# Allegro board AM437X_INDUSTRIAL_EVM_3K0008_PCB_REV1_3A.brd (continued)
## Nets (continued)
DGND: C3.2 C4.2 C5.2 C6.2 C7.2 C8.2 C9.2 C10.2 C11.2 C12.2 C13.2 C14.2 C16.2 C17.2 C18.2 C19.2 C20.2 C21.2 C22.2 C23.2 C24.2 C25.2 C26.2 C27.2(NEG) C28.2 C29.2 C30.2 C31.2 C32.2 C33.2 C34.2 C37.2 C38.2 C39.2 C40.2 C41.2 C43.2 C44.2 C45.2 C46.2 C47.2 C48.2 C49.2 C50.2 C52.2 C53.2 C58.2 C59.2 C60.2 C61.2 C62.2 C63.2 C64.2 C65.2 C66.2 C68.2 C69.2 C70.2 C71.2 C72.2 C73.2 C74.2 C75.2 C76.2 C77.2 C78.2 C79.2 C80.2 C81.2 C82.2 C83.2 C84.2 C85.2 C86.2 C87.2 C89.2 C90.2 C91.2 C92.2 C93.2 C95.2 C96.2 C97.2 C98.2 C100.2 C101.2 C102.2 C103.2 C104.2 C105.2 C106.2 C107.2 C108.2 C109.2 C110.2 C111.2 C112.2 C113.2 C114.2 C115.2 C116.2 C117.2 C118.2 C119.2 C120.2 C121.1 C122.1 C123.2 C124.2 C125.2 C126.2 C127.2 C128.2 C129.1 C130.1 C131.2(NEG) C132.2 C133.2 C134.2 C136.2 C137.1 C138.2 C139.2 C140.2 C141.2 C142.2 C143.2 C144.2 C145.2 C146.2 C147.2 C148.2 C149.2 C150.2 C151.2 C152.2 C153.2 C154.2 C155.2 C156.2 C157.2 C158.2 C159.2 C160.2 C161.2 C162.2 C163.2 C164.2 C165.2 C166.2 C167.2 C168.2 C169.2 C170.2 C171.2 C172.2 C173.2 C174.2 C175.2 C176.2 C177.2 C178.2 C179.2 C180.2 C181.2 C182.2 C183.2 C184.2 C185.2 C186.2 C187.2 C188.1 C189.2 C190.2 C191.2 C192.2 C193.2 C194.2 C195.2 C196.2 C197.2 C198.2 C199.2 C200.2 C201.2 C202.2 C203.2 C204.2 C205.2 C206.2 C207.2 C208.2 C209.2 C210.2 C211.2 C212.2 C213.2 C214.2 C215.2 C216.2 C218.2 C219.2 C220.2 C221.2 C222.2 C223.2 C224.2 C225.2 C226.2 C227.2 C228.2 C229.2 C230.2 C231.2 C232.2 C233.2 C234.2 C235.2 C236.2 C237.2 C238.2 C239.2 C240.2 C241.2 C242.2 C244.2 C245.1 C246.1 C249.2 C250.1 C251.1 C252.2 C254.2 C255.2 C256.2 C257.2 C258.2 C259.2 C260.1 C261.2 C262.2 C263.2 C264.2 C265.2 C266.2 C267.2 C268.2 C269.2 C271.2(NEG) C272.2 C273.2 C274.1 C275.1 C276.2 C277.2 C278.2 C279.2 C280.2 C281.2 C282.2 C283.2 C284.2 C285.2 C286.2 C287.2 C288.2 C289.2 C290.2 C291.2 C292.2 C293.2 C294.2 C295.2 C296.2 C297.2 C299.2 C301.2 C302.2 C303.2 C304.2 C307.2 C309.2 C311.2 C312.2 C314.2 C315.2 C316.2 C318.2 C319.2 C320.2 C321.2 C322.2(NEG) C323.2 C324.2 C325.2 C326.2 C327.2 C328.2 C329.2 C330.2 C333.2 C334.2 C335.2 C336.2 C337.2 C338.2 C339.2 C340.2(NEG) C341.2 C342.2 C343.2 C344.2 C345.2 C346.2 C347.2 C348.2 C349.2 C350.2 C351.2 C352.2 D1.2(ANODE) D2.1(CATHODE) D11.2(ANODE) D13.2(ANODE) D14.2(ANODE) D15.1(CATHODE) D16.2(ANODE) D18.2(ANODE) D21.2(ANODE) D22.2(ANODE) FB12.2 J1.17 J1.29 J1.30 J3.10 J4.1 J4.12 J4.13 J5.5 J5.7 J6.8 J7.8(GND#8) J7.12(GND#12) J7.16(GND#16) J7.20(GND#20) J8.2 J9.8 J12.2 J12.3 J13.2 J15.6 J16.22 J16.39 J16.40 J16.59 J16.60 J18.5(GND) J19.6(VSS) J19.9(GND) J19.11(GND3) J19.12(GND4) J19.13(GND5) J19.14(GND6) J19.15(GND7) J19.16(GND8) Q1.S(SOURCE) Q2.S(SOURCE) Q3.S(SOURCE) Q4.S(SOURCE) Q5.S(SOURCE) Q6.S(SOURCE) Q7.S(SOURCE) Q8.S(SOURCE) R1.1(P1) R7.1(P1) R9.1(P1) R11.1(P1) R17.1(P1) R18.1(P1) R19.2 R32.2 R33.1(P1) R34.1(P1) R44.1(P1) R45.1(P1) R46.1(P1) R51.1(P1) R53.1(P1) R55.1(P1) R57.1(P1) R81.1(P1) R93.2 R94.1(P1) R108.1(P1) R112.1(P1) R122.1(P1) R127.1(P1) R130.1(P1) R156.1(P1) R160.1(P1) R162.1(P1) R166.1(P1) R169.1(P1) R172.1(P1) R175.1(P1) R176.1(P1) R181.1(P1) R182.1(P1) R185.1(P1) R191.1(P1) R192.1(P1) R197.2(P2) R198.1(P1) R202.1(P1) R212.1(P1) R213.1(P1) R274.1(P1) R276.1(P1) R278.1(P1) R301.1(P1) R304.1(P1) R314.1(P1) R315.1(P1) R316.1(P1) R317.1(P1) R318.1(P1) R319.1(P1) R320.1(P1) R321.1(P1) R322.1(P1) R328.1(P1) R329.1(P1) R330.1(P1) R331.1(P1) R332.1(P1) R333.1(P1) R334.1(P1) R335.1(P1) R340.1(P1) R341.1(P1) R342.1(P1) R362.1(P1) R366.1(P1) R369.1(P1) R372.1(P1) R394.1(P1) R397.1(P1) R398.1(P1) R429.1(P1) R433.1(P1) R444.1(P1) R452.1(P1) R460.2(P2) R464.1(P1) R474.2 R476.1(P1) R504.1(P1) R509.1(P1) R511.1(P1) R513.2(P2) R515.2(P2) R518.1(P1) R539.1(P1) R541.2(P2) R543.1(P1) R549.1(P1) R550.1(P1) R551.1(P1) R553.1(P1) R554.1(P1) R555.1(P1) R556.1(P1) R557.1(P1) R566.2(P2) SW1.3 SW1.4 SW2.1 SW2.2 TP1.1 TP9.1 TP11.1 TP16.1 U3.7(GND) U4.28(GND) U4.TH_PD(THRM) U5.7(A2) U5.8(G\) U5.9(A0) U5.10(A1) U5.16(GND) U6.2(DIR) U6.11(GND#11) U6.12(GND#12) U6.13(GND#13) U7.TPAD U8.3(GND) U9.10(GND) U10.7(GND) U11.A1(GND#A1) U11.A25(GND#A25) U11.AA23(TEST_EN) U11.AE1(GND#AE1) U11.AE25(GND#AE25) U11.H15(GND#H15) U11.H18(GND#H18) U11.J9(GND#J9) U11.J12(GND#J12) U11.J15(GND#J15) U11.J17(GND#J17) U11.K9(GND#K9) U11.K11(GND#K11) U11.K12(GND#K12) U11.K14(GND#K14) U11.K15(GND#K15) U11.L8(GND#L8) U11.L9(GND#L9) U11.L11(GND#L11) U11.L15(GND#L15) U11.L17(GND#L17) U11.L18(GND#L18) U11.M10(GND#M10) U11.M11(GND#M11) U11.M13(GND#M13) U11.M15(GND#M15) U11.M16(GND#M16) U11.N10(GND#N10) U11.N11(GND#N11) U11.N12(GND#N12) U11.N13(GND#N13) U11.N14(GND#N14) U11.N15(GND#N15) U11.P8(GND#P8) U11.P9(GND#P9) U11.P10(GND#P10) U11.P11(GND#P11) U11.P12(GND#P12) U11.P13(GND#P13) U11.P14(GND#P14) U11.P15(GND#P15) U11.R12(GND#R12) U11.R15(GND#R15) U11.R17(GND#R17) U11.R18(GND#R18) U11.T12(GND#T12) U11.T15(GND#T15) U11.T17(GND#T17) U11.U8(GND#U8) U11.U9(GND#U9) U11.U10(GND#U10) U11.U11(GND#U11) U11.U12(GND#U12) U11.U13(GND#U13) U11.U14(GND#U14) U11.U16(GND#U16) U11.U17(GND#U17) U11.U18(GND#U18) U11.U19(GND#U19) U11.V9(GND#V9) U11.V10(GND#V10) U11.V11(GND#V11) U11.V12(GND#V12) U11.V13(GND#V13) U11.V14(GND#V14) U11.V18(GND#V18) U11.W23(VSSA_USB) U12.TPAD U13.1(GND.1) U13.5(GND.2) U13.10(AGND) U13.11(GND.3) U13.13(TEST) U13.15(GND.4) U13.25(GND.5) U13.35(GND.6) U13.47(GND.7) U13.51(GND.8) U14.7(GND) U15.7(GND) U16.5(VSS) U16.7(NC1) U17.7(GND) U18.2(V-) U19.2(V-) U20.A9(VSS#A9) U20.B1(VSSQ#B1) U20.B3(VSS#B3) U20.B9(VSSQ#B9) U20.D1(VSSQ#D1) U20.D8(VSSQ#D8) U20.E1(VSS#E1) U20.E2(VSSQ#E2) U20.E8(VSSQ#E8) U20.F9(VSSQ#F9) U20.G1(VSSQ#G1) U20.G8(VSS#G8) U20.G9(VSSQ#G9) U20.J2(VSS#J2) U20.J8(VSS#J8) U20.M1(VSS#M1) U20.M9(VSS#M9) U20.P1(VSS#P1) U20.P9(VSS#P9) U20.T1(VSS#T1) U20.T9(VSS#T9) U21.A9(VSS#A9) U21.B1(VSSQ#B1) U21.B3(VSS#B3) U21.B9(VSSQ#B9) U21.D1(VSSQ#D1) U21.D8(VSSQ#D8) U21.E1(VSS#E1) U21.E2(VSSQ#E2) U21.E8(VSSQ#E8) U21.F9(VSSQ#F9) U21.G1(VSSQ#G1) U21.G8(VSS#G8) U21.G9(VSSQ#G9) U21.J2(VSS#J2) U21.J8(VSS#J8) U21.M1(VSS#M1) U21.M9(VSS#M9) U21.P1(VSS#P1) U21.P9(VSS#P9) U21.T1(VSS#T1) U21.T9(VSS#T9) U22.2(V-) U23.14(GND#14) U23.20(GND#20) U23.28(GND#28) U23.TPAD U24.2(V-) U25.4(PGND) U25.8(GND) U25.11(PWRPD) U26.6(SENSE4H) U26.12(GND) U26.TPAD U27.5(GND) U28.2(GND) U29.C1(GND) U30.2(GND) U31.2(GND) U32.1(A0) U32.2(A1) U32.3(A2) U32.4(VSS) U33.5(GND1) U33.10(GND2) U34.2(GND) U34.5(DIR) U35.A2(AGND) U35.C1(SENSEM) U35.C3(PGND#C3) U35.C4(PGND#C4) U35.D4(PGND#D4) U36.3(GND) U37.13(VSS_PS) U37.29(VSS) U37.49(P_GND) U38.3(2DIR) U38.8(GND#8) U38.9(GND#9) U38.14(2O\E\) U38.15(1O\E\) U39.10(GND) U40.C1(GND) U41.5(GND) U42.3(GND) U43.3(GND) U44.3(GND) U45.8(GND#8) U45.9(GND#9) U46.10(GND) U47.4(GND) U48.3(GND) U49.5(GND) U50.3(GND) U51.3(GND) U52.C1(GND) U53.C1(GND) U54.3(GND) U55.5(GND) U56.3(GND) U57.5(GND) U58.11(GND#11) U58.12(GND#12) U58.13(GND#13) U59.4(GND)
GND_ETH1: C121.2 C122.2 J4.SHLD1 J4.SHLD2
GND_OSC0: C35.2 C36.2 R566.1(P1) U11.B24(VSS_OSC)
GND_OSC1: C243.2 C248.2 U11.AD4(VSS_RTC)
GNDA_ADC: C54.2 C55.2 C56.2 C57.2 C217.2 J1.39 J1.40 J2.3 R58.1 R64.1 R68.1 R202.2(P2) R444.2(P2) U11.AC15(VSSA_ADC) U11.AD15(ADC1_VREFN) U11.AE14(ADC0_VREFN)
GNDUSBJ: FB12.1 J18.S1 J18.S2 J18.S3 J18.S4
V1_5D: C231.1 C233.1 C234.1 C236.1 C240.1 C241.1 C247.1 C276.1 C280.1 R313.2(P2) R470.1 R486.1(P1) R494.2(P2) U11.K7(VDD_DDR#K7) U11.K8(VDD_DDR#K8) U11.M7(VDD_DDR#M7) U11.M8(VDD_DDR#M8) U11.N7(VDD_DDR#N7) U11.N8(VDD_DDR#N8) U11.R6(VDD_DDR#R6) U11.R7(VDD_DDR#R7) U11.R8(VDD_DDR#R8) U11.T7(VDD_DDR#T7) U11.T8(VDD_DDR#T8) U11.V7(VDD_DDR#V7) U11.V8(VDD_DDR#V8)
V1_5DREG: C269.1 C273.1 L8.2 R480.2(P2) U52.A2(VIN#A2) U52.B2(VIN#B2)
V1_8D: C139.1 C168.1 FB1.2 Q1.G(GATE) R1.2(P2) R229.2(P2) R309.2(P2) R379.1(P1) R479.2(P2) U33.3(VDD)
V1_8D_AM437X: C31.1 C32.1 C158.1 C159.1 C160.1 C192.1 FB1.1 FB6.2 FB8.1 FB9.1 FB10.1 FB11.2 FB14.2 R142.2(P2) R149.2(P2) U11.C23(VDDS_OSC)
V1_8DADC: C119.1 C120.1 R110.1(P1) R126.1(P1) U28.5(VREF)
V1_8DEN: R237.1(P1) R359.2(P2) R490.2(P2) U26.15(R\E\S\E\T\1\)
V1_8DREG: C171.1 C175.1 L6.2 R360.2(P2) R415.2(P2) U40.A2(VIN#A2) U40.B2(VIN#B2)
V1_8FTDI: C61.1 C73.1 C76.1 C239.1 C258.1 U13.12(VCORE.1) U13.37(VCORE.2) U13.49(VREGOUT) U13.64(VCORE.3)
V2_5MTR: R194.2(P2) R196.2(P2) R208.2(P2) R210.2(P2) U56.2(OUT)
V2_8A: C2.1 C15.1 J5.3 R13.2(P2)
V2_8D: C13.1 C25.1 C123.1 C140.1 C145.1 C146.1 J5.12 R13.1(P1) R15.2(P2) R16.2(P2) R303.1(P1) R305.2(P2) TP17.1 U6.23(VCCB#23) U6.24(VCCB#24) U31.3(VCCA) U34.6(VCCB) U38.16(VCCB)
V2_8D_EN: R309.1(P1) U30.3(EN)
V2_8D_FB: C135.2 R301.2(P2) R306.1(P1) U30.5(FB)
V2_8D_OUT: C132.1 C135.1 R303.2(P2) R306.2(P2) U30.6(OUT)
V3_3D: C18.1 C19.1 C20.1 C34.1 C37.1 C41.1 C63.1 C64.1 C113.1 C115.1 C116.1 C126.1 C127.1 C131.1(POS) C133.1 C134.1 C141.1 C144.1 C147.1 C148.1 C150.1 C156.1 C157.1 C166.1 C169.1 C178.1 C183.1 C185.1 C190.1 C194.1 C196.1 C208.1 C263.1 C264.1 C267.1 C274.2 C275.2 C319.1 C320.1 FB5.1 FB7.2 J7.5(TVDD) J16.1 J19.4(VDD) Q10.S(SOURCE) R20.2 R23.2(P2) R24.2(P2) R25.2(P2) R26.2(P2) R27.2(P2) R28.2(P2) R29.2(P2) R30.2(P2) R31.1(P1) R35.2(P2) R36.2(P2) R37.2(P2) R38.2(P2) R39.2(P2) R40.2(P2) R41.2(P2) R42.2(P2) R43.1(P1) R47.2(P2) R48.2(P2) R49.2(P2) R50.1(P1) R54.2(P2) R56.1(P1) R69.2(P2) R75.2(P2) R77.2(P2) R87.2(P2) R96.2(P2) R100.2(P2) R101.1(P1) R106.1(P1) R125.1(P1) R131.1(P1) R145.2(P2) R231.2(P2) R232.2(P2) R233.2(P2) R235.1 R236.2(P2) R244.2(P2) R266.2(P2) R267.2(P2) R297.2(P2) R299.1(P1) R300.2(P2) R310.2(P2) R325.2(P2) R343.2(P2) R346.1(P1) R347.2(P2) R355.2(P2) R380.2(P2) R401.2(P2) R402.2(P2) R403.2(P2) R411.2(P2) R412.2(P2) R418.2(P2) R420.2(P2) R424.2(P2) R426.2(P2) R438.2(P2) R446.1(P1) R451.2(P2) R455.2(P2) R456.2(P2) R458.2(P2) R462.2(P2) R472.2(P2) R475.2(P2) R495.1(P1) R519.2(P2) R542.2(P2) R548.2(P2) U1.1(A) U2.1(A) U5.1(VCC) U6.1(VCCA) U7.21(VDD33_IO) U8.5(VCC) U9.20(VCC) U12.21(VDD33_IO) U25.10(VIN) U27.10(VCC) U30.1(IN) U31.7(VCCB) U32.8(VCC) U33.6(VDDOUT1) U33.7(VDDOUT2) U34.1(VCCA) U35.A1(AVIN) U35.A4(VIN) U35.D1(VDD) U38.1(VCCA) U38.2(1DIR) U39.20(VCC) U41.8(VCCB) U43.5(VCC) U44.5(VCC) U45.16(VCCB) U46.2(VCC) U48.5(VCC) U49.1(VCCA) U49.3(A2) U50.5(VCC) U51.5(VCC) U55.2(R\E\) U55.3(DE) U55.8(VCC) U57.8(VCC) U58.1(VCCA) U59.1(VCC)
V3_3D_AM437X: C47.1 C48.1 C52.1 C53.1 C59.1 C181.1 C184.1 C189.1 C193.1 C195.1 C201.1 C204.1 C223.1 C229.1 C252.1 C256.1 FB7.1 U11.F16(VDDSHV7) U11.F22(VDDSHV5) U11.G10(VDDSHV10#G10) U11.G11(VDDSHV9#G11) U11.G13(VDDSHV8#G13) U11.G14(VDDSHV8#G14) U11.G16(VDDSHV6#G16) U11.G17(VDDSHV6#G17) U11.H8(VDDSHV11#H8) U11.H9(VDDSHV11#H9) U11.H10(VDDSHV10#H10) U11.H11(VDDSHV9#H11) U11.H17(VDDSHV6#H17) U11.J7(VDDSHV1#J7) U11.J8(VDDSHV1#J8) U11.J18(VDDSHV3#J18) U11.K17(VDDSHV3#K17) U11.K18(VDDSHV3#K18) U11.N18(VDDSHV3#N18) U11.N19(VDDSHV3#N19) U11.P18(VDDSHV3#P18) U11.U20(VDDA_3P3V_USB1) U11.V16(VDDSHV2#V16) U11.V17(VDDSHV2#V17) U11.W16(VDDSHV2#W16) U11.W18(VDDSHV3#W18) U11.W20(VDDA_3P3V_USB0)
V3_3D_PRUETH0JCK: C153.1 C155.1 J6.3 J6.4 R380.1(P1)
V3_3D_PRUETH1JCK: C215.1 C222.1 J9.3 J9.4 R438.1(P1)
V3_3DREG: C114.1 C124.1 C281.1 L4.2 R224.2(P2) R228.2(P2) R234.2(P2) R237.2(P2) R273.2(P2) R302.2(P2) U26.14(VCC) U54.5(VCC)
V3_3FTDI: C78.1 C170.1 C209.1 C227.1 C228.1 C235.1 C249.1 C259.1 C260.2 C265.1 FB15.2 FB16.2 R135.2(P2) R178.2(P2) R451.1(P1) U13.20(VCCIO.1) U13.31(VCCIO.2) U13.42(VCCIO.3) U13.50(VREGIN) U13.56(VCCIO.4) U16.6(NC2) U16.8(VCC) U41.1(VCCA) U45.1(VCCA) U45.2(1DIR) U45.3(2DIR) U49.8(VCCB)
V3_3MTR: R190.2(P2) R201.2 R204.2 R214.2 R223.2 R496.1(P1) R500.2 R505.2
V3_3MTRB: C87.1 R190.1(P1) U23.15(V3P3OUT)
V5_0D: C110.1 C117.1 C128.1 C254.1 C336.1 FB17.1 J1.27 J1.28 J15.1 J16.2 L7.2 R2.2(P2) R3.2(P2) R164.2(P2) R280.1(P1) R281.1(P1) R282.1(P1) R283.1(P1) R284.1(P1) R285.1(P1) R286.1(P1) R287.1(P1) R544.2(P2) R545.2(P2) R546.2(P2) R547.2(P2) R552.2(P2) R560.2(P2) R565.2(P2) U28.4(VIN) U58.23(VCCB#23) U58.24(VCCB#24)
V5_0DENCOD: FB17.2 R483.1(P1)
V5_0VOP: C16.1 C24.1 C138.1 U4.15(5VOP) U36.5(VCC)
V24_0D: C12.1 C45.1 C70.1 C74.1 C81.1 C95.1 C96.1 C97.1 C98.1 C154.1 C322.1(POS) D21.1(CATHODE) F1.2 J1.2 J1.4 J1.6 J1.8 J1.10 J1.12 J1.14 J1.16 J11.1 R338.2(P2) TP14.1 U3.2(VIN) U10.2(VIN) U14.2(VIN) U15.2(VIN) U17.2(VIN)
V24_0MTR: C99.1 C303.1 C326.1 C327.1 C337.1 C339.1 C340.1(POS) D17.1(CATHODE) D18.1(CATHODE) J11.2 R154.2(P2) R485.1(P1) TP15.1 U23.4(VM#4) U23.11(VM#11)
VDD_CORE: C202.1 C205.1 C213.1 C219.1 C220.1 C221.1 C224.1 C230.1 C257.1 C266.1 C271.1(POS) R139.2(P2) R227.2(P2) R488.1(P1) U11.J10(VDD_CORE#J10) U11.J11(VDD_CORE#J11) U11.L12(VDD_CORE#L12) U11.L14(VDD_CORE#L14) U11.M9(VDD_CORE#M9) U11.M12(VDD_CORE#M12) U11.M14(VDD_CORE#M14) U11.N9(VDD_CORE#N9) U11.N16(VDD_CORE#N16) U11.N17(VDD_CORE#N17) U11.P16(VDD_CORE#P16) U11.P17(VDD_CORE#P17) U11.R9(VDD_CORE#R9) U11.R11(VDD_CORE#R11) U11.R14(VDD_CORE#R14) U11.T9(VDD_CORE#T9) U11.T11(VDD_CORE#T11) U11.T14(VDD_CORE#T14) U11.T18(VDD_CORE#T18) U11.T19(VDD_CORE#T19) U11.U15(VDD_CORE#U15) U11.V15(VDD_CORE#V15) U11.W12(VDD_CORE#W12) U11.W13(VDD_CORE#W13)
VDD_CORE_EN: R234.1(P1) R482.2(P2) U26.17(R\E\S\E\T\3\)
VDD_COREREG: C268.1 C272.1 L9.2 R492.2(P2) U53.A2(VIN#A2) U53.B2(VIN#B2)
VDD_MPU: C27.1(POS) C39.1 C40.1 C172.1 C197.1 C203.1 C207.1 R230.2(P2) R358.1(P1) TP7.1 U11.H13(VDD_MPU#H13) U11.H14(VDD_MPU#H14) U11.H16(VDD_MPU#H16) U11.J13(VDD_MPU#J13) U11.J14(VDD_MPU#J14) U11.J16(VDD_MPU#J16) U11.K19(VDD_MPU#K19) U11.K20(VDD_MPU#K20) U11.L19(VDD_MPU#L19) U11.L20(VDD_MPU#L20) U11.M17(VDD_MPU#M17) U11.M18(VDD_MPU#M18)
VDD_MPU_EN: R228.1(P1) R324.2(P2) U26.18(R\E\S\E\T\4\)
VDD_MPU_OUT: L5.1 U35.B3(SW#B3) U35.B4(SW#B4)
VDD_MPU_SENSE: C165.1 L5.2 R52.1(P1) R358.2(P2)
VDD_MPU_SENSEP: R52.2(P2) U35.B1(SENSEP)
VDD_TAMPER: C60.1 R139.1(P1) U11.AD9(VDD_TPM)
VDDA1P8_PMLDO: R463.1(P1) U11.D6(VDDA1P8_PMLDO)
VDDA3P3_PMLDO: R456.1(P1) U11.F8(VDDA3P3_PMLDO)
VDDA_ADC: C217.1 FB14.1 U11.AB12(VDDA_TS_ADC)
VDDA_MC_ADC: C211.1 FB11.1 U11.Y16(VDDA_MC_ADC)
VDDR_VREF: C112.1 C307.1 C311.1 C312.1 C313.2 C317.2 C330.1 U20.H1(VREFDQ) U20.M8(VREFCA) U21.H1(VREFDQ) U21.M8(VREFCA) U25.6(REFOUT)
VDDR_VTT: C103.1 C104.1 C106.1 C335.1 C338.1 C342.1 R199.1(P1) R205.1(P1) R206.1(P1) R216.1(P1) R217.1(P1) R218.1(P1) R219.1(P1) R220.1(P1) R221.1(P1) R225.2(P2) R503.1(P1) R516.1(P1) R517.1(P1) R520.1(P1) R521.1(P1) R522.1(P1) R527.1(P1) R528.1(P1) R529.1(P1) R530.1(P1) R531.1(P1) R532.1(P1) R533.1(P1) R534.1(P1) R535.1(P1) U25.3(VO)
VDDS_CTM: FB6.1 U11.AD12(VDDS_CTM)
VDDS_DDR: C80.1 C102.1 C105.1 C107.1 C111.1 C277.1 C278.1 C279.1 C282.1 C283.1 C284.1 C285.1 C288.1 C289.1 C290.1 C291.1 C292.1 C294.1 C295.1 C296.1 C297.1 C299.1 C301.1 C302.1 C304.1 C306.2 C313.1 C314.1 C315.1 C316.1 C317.1 C318.1 C323.1 C324.1 C328.1 C329.1 C341.1 R226.2(P2) R494.1(P1) U20.A1(VDDQ#A1) U20.A8(VDDQ#A8) U20.B2(VDD#B2) U20.C1(VDDQ#C1) U20.C9(VDDQ#C9) U20.D2(VDDQ#D2) U20.D9(VDD#D9) U20.E9(VDDQ#E9) U20.F1(VDDQ#F1) U20.G7(VDD#G7) U20.H2(VDDQ#H2) U20.H9(VDDQ#H9) U20.K2(VDD#K2) U20.K8(VDD#K8) U20.N1(VDD#N1) U20.N9(VDD#N9) U20.R1(VDD#R1) U20.R9(VDD#R9) U21.A1(VDDQ#A1) U21.A8(VDDQ#A8) U21.B2(VDD#B2) U21.C1(VDDQ#C1) U21.C9(VDDQ#C9) U21.D2(VDDQ#D2) U21.D9(VDD#D9) U21.E9(VDDQ#E9) U21.F1(VDDQ#F1) U21.G7(VDD#G7) U21.H2(VDDQ#H2) U21.H9(VDDQ#H9) U21.K2(VDD#K2) U21.K8(VDD#K8) U21.N1(VDD#N1) U21.N9(VDD#N9) U21.R1(VDD#R1) U21.R9(VDD#R9) U25.2(VLDOIN)
VDDS_TAMPER: C62.1 R142.1(P1) U11.AD8(VDDS_TPM)
ADC0_VREFP: C56.1 C57.1 R126.2(P2) U11.AD14(ADC0_VREFP)
ADC1_VREFP: C54.1 C55.1 R110.2(P2) U11.AE15(ADC1_VREFP)
AM437X_AIN0: J1.31 R450.1(P1)
AM437X_AIN1: J1.33 R440.1(P1)
AM437X_AIN2: J1.35 R435.1(P1)
AM437X_AIN3: J1.37 R436.1(P1)
AM437X_AIN4: J1.32 R104.1(P1)
AM437X_AIN5: J1.34 R103.1(P1)
AM437X_AIN6: J1.36 R129.1(P1)
AM437X_AIN7: J1.38 R124.1(P1)
AM437X_CAM0_DATA0: R264.2(P2) R326.2(P2) U11.AE18(CAM0_DATA0)
AM437X_CAM0_DATA1: R253.2(P2) R327.2(P2) R375.2(P2) U11.AB18(CAM0_DATA1/EHRPWM3_SYNCO)
AM437X_CAM0_DATA2: U6.5(A3) U11.Y18(CAM0_DATA2)
AM437X_CAM0_DATA3: U6.6(A4) U11.AA18(CAM0_DATA3)
AM437X_CAM0_DATA4: R364.1(P1) U6.7(A5) U11.AE19(CAM0_DATA4/EHRPWM3A)
AM437X_CAM0_DATA5: R363.1(P1) U6.8(A6) U11.AD19(CAM0_DATA5/EHRPWM3B)
AM437X_CAM0_DATA6: R247.2(P2) U6.9(A7) U11.AE20(CAM0_DATA6)
AM437X_CAM0_DATA7: U6.10(A8) U11.AD20(CAM0_DATA7)
AM437X_CAM0_HSYNC: U11.AE17(CAM0_HSYNC) U38.7(2A2)
AM437X_CAM0_PCLK: U11.AC20(CAM0_PCLK) U34.3(A)
AM437X_CAM0_VSYNC: U11.AD18(CAM0_VSYNC) U38.6(2A1)
AM437X_CAM1_DATA2: R277.1(P1) U11.AD21(CAM1_DATA2)
AM437X_CAM1_DATA3: R258.2(P2) U11.AE22(CAM1_DATA3)
AM437X_CAM1_DATA5: R255.2(P2) U11.AE23(CAM1_DATA5)
AM437X_CAM1_DATA6: R417.2(P2) R431.2(P2) U11.AD23(CAM1_DATA6)
AM437X_CAM1_DATA7: R254.2(P2) U11.AE24(CAM1_DATA7)
AM437X_CAM1_DATA8: R80.1(P1) R265.2(P2) U11.AD24(CAM1_DATA8/GPIO)
AM437X_CAM1_WEN: R275.1(P1) U11.AB25(CAM1_WEN)
AM437X_DCAN0_RX: C176.1 R386.1 U11.L22(UART1_RTSN/DCAN0_RX)
AM437X_DCAN0_TX: R387.1 U11.K22(UART1_CTSN/DCAN0_TX)
AM437X_EHRPWM0_SYNCI: J16.6 U11.P25(SPI4_SCLK/EHRPWM0_SYNCI)
AM437X_EHRPWM0_SYNCO: J16.10 U11.D11(GPMC_AD11/EHRPWM0_SYNCO)
AM437X_EHRPWM0B: J16.4 R83.1(P1) U11.AC23(CAM1_VSYNC/EHRPWM0B)
AM437X_EHRPWM1B: J16.12 R375.1(P1) U11.AC25(CAM1_FIELD/EXT_HW_TRIG)
AM437X_EHRPWM2A: J16.14 U11.B10(GPMC_AD8/EHRPWM2A)
AM437X_EHRPWM2B: J16.16 U11.A10(GPMC_AD9/EHRPWM2B)
AM437X_EHRPWM4A: R70.1(P1) U11.H25(UART3_RXD/EHRPWM4A)
AM437X_EHRPWM4B: R187.1(P1) U11.H24(UART3_TXD/EHRPWM4B)
AM437X_EHRPWM5A: R132.1(P1) U11.H22(UART3_CTSN/EHRPWM5A)
AM437X_EHRPWM012_TRPZONE: J16.8 R73.2(P2) R74.2(P2) R383.2(P2)
AM437X_GPIO_CAM: R350.2(P2) U11.AD17(CAM0_WEN/GPIO)
AM437X_GPIO_IND_LDN: R105.2(P2) U11.B14(MII1_CRS/SPI1_GPIO)
AM437X_HDQ: R138.1(P1) R243.1(P1) U11.K24(UART3_RTSN/EHRPWM5B)
AM437X_I2C0_SCL: R356.2(P2) R424.1(P1) R425.2(P2) U11.Y22(I2C_SCL0)
AM437X_I2C0_SDA: R354.2(P2) R418.1(P1) R419.2(P2) U11.AB24(I2C_SDA0)
AM437X_I2C2_SCL: R96.1(P1) R97.2(P2) R430.2(P2) U11.AC21(CAM1_DATA1/I2C2_SCL)
AM437X_I2C2_SDA: R98.2(P2) R100.1(P1) R432.2(P2) U11.AB20(CAM1_DATA0/I2C2_DTA)
AM437X_LCD_AC_BIAS_EN: R8.1(P1) R49.1(P1) R259.2(P2) R341.2(P2) U11.A24(LCD_AC_BIAS_EN)
AM437X_LCD_DATA6: J16.49 R406.1(P1) U11.C20(LCD_D6)
AM437X_LCD_DATA7: R408.1(P1) U11.E19(LCD_D7)
AM437X_LCD_HSYNC: R48.1(P1) R260.2(P2) R279.2(P2) R342.2(P2) U11.A23(LCD_HSYNC)
AM437X_LCD_PCLK: R10.2(P2) U11.A22(LCD_PCLK)
AM437X_LCD_VSYNC: R12.1(P1) R47.1(P1) R340.2(P2) U11.B23(LCD_VSYNC)
AM437X_MCASP0_ACLKR: R251.1(P1) U11.L23(MCASP0_ACLKR/EQEP0A_IN) U58.3(A1)
AM437X_MCASP0_AHCLKR: R252.1(P1) U11.M24(MCASP0_AHCLKR)
AM437X_MCASP0_AHCLKX: R240.1(P1) U11.L24(MCASP0_AHCLKX/EQEP0_STROBE) U58.6(A4)
AM437X_MCASP0_AXR1: R242.1(P1) U11.M25(MCASP0_AXR1/EQEP0_INDEX) U58.5(A3)
AM437X_MCASP0_FSR: R250.1(P1) U11.K23(MCASP0_FSR/EQEP0B_IN) U58.4(A2)
AM437X_MMC0_CLK: R179.2(P2) U11.D1(MMC0_CLK/MMC0_CLK)
AM437X_MMC0_CMD: R177.2(P2) U11.D2(MMC0_CMD/MMC0_CMD)
AM437X_MMC0_DAT0: R174.2(P2) R238.1(P1) U11.C1(MMC0_DAT0/MMC0_DAT0)
AM437X_MMC0_DAT1: R167.2(P2) R249.1(P1) U11.C2(MMC0_DAT1/MMC0_DAT1)
AM437X_MMC0_DAT2: J16.37 R161.2(P2) R514.2(P2) U11.B2(MMC0_DAT2/MMC0_DAT2)
AM437X_MMC0_DAT3: R158.2(P2) R239.1(P1) U11.B1(MMC0_DAT3/MMC0_DAT3)
AM437X_MMC0_SDCD: R84.2(P2) U11.R25(SPI0_CS1/MMC0_SDCD)
AM437X_OSC0_IN: R92.1(P1) U11.C25(OSC0_IN)
AM437X_OSC0_OUT: R91.1(P1) U11.B25(OSC0_OUT)
AM437X_PROFI_RXD: J16.47 U11.K21(UART1_RXD)
AM437X_PROFI_TXD: J16.45 U11.L21(UART1_TXD)
AM437X_PRU0_ENDAT0_CLK: R427.2(P2) R428.2(P2) U11.N24(MCASP0_ACLKX/PRU0_ENDAT0_CLK)
AM437X_PRU0_ENDAT0_OUT: R422.2(P2) R423.2(P2) U11.N22(MCASP0_FSX/PRU0_ENDAT0_OUT)
AM437X_PRU0_ENDAT0_OUTEN: J16.35 R526.2(P2) U11.H23(MCASP0_AXR0/PRU0_ENDAT0_OUTEN)
AM437X_PRUETH0_COL: R351.2(P2) U11.D25(PRINT_NSTROBE/PR1_MII0_COL)
AM437X_PRUETH0_CRS: R65.2(P2) U11.G20(PRINT_MNA/PR1_MII0_CRS)
AM437X_PRUETH0_MRCLK: R76.2(P2) U11.C17(LCD_D14/PR1_MII0_MR_CLK) U39.16(1Y2)
AM437X_PRUETH0_RXD0: R349.2(P2) U11.B18(LCD_D11/PR1_MII0_RXD0) U39.9(2Y1)
AM437X_PRUETH0_RXD1: R344.2(P2) U11.A18(LCD_D10/PR1_MII0_RXD1) U39.7(2Y2)
AM437X_PRUETH0_RXD2: R339.2(P2) U11.B19(LCD_D9/PR1_MII0_RXD2) U39.5(2Y3)
AM437X_PRUETH0_RXD3: R337.2(P2) U11.A19(LCD_D8/PR1_MII0_RXD3) U39.3(2Y4)
AM437X_PRUETH0_RXDV: R63.2(P2) R67.2(P2) U11.D17(LCD_D15/PR1_MII0_RXDV) U39.18(1Y1)
AM437X_PRUETH0_RXER: R59.2(P2) U11.D19(LCD_D13/PR1_MII0_RXER) U39.14(1Y3)
AM437X_PRUETH0_RXLINK: R434.2(P2) U11.C19(LCD_D12/PR1_MII0_RXLINK) U39.12(1Y4)
AM437X_PRUETH0_TXCLK: R410.2(P2) U9.3(2Y4) U11.B22(LCD_D0/PR1_MII0_MT_CLK)
AM437X_PRUETH0_TXD0: R391.2(P2) U9.14(1Y3) U11.B20(LCD_D5/PR1_MII0_TXD0)
AM437X_PRUETH0_TXD1: R378.2(P2) U9.12(1Y4) U11.A20(LCD_D4/PR1_MII0_TXD1)
AM437X_PRUETH0_TXD2: R377.2(P2) U9.9(2Y1) U11.C21(LCD_D3/PR1_MII0_TXD2)
AM437X_PRUETH0_TXD3: R390.2(P2) U9.7(2Y2) U11.B21(LCD_D2/PR1_MII0_TXD3)
AM437X_PRUETH0_TXEN: R404.2(P2) R405.2(P2) U9.5(2Y3) U11.A21(LCD_D1/PR1_MII0_TXEN)
AM437X_PRUETH1_MRCLK: R465.2(P2) R466.2(P2) U11.F6(GPMC_A7/PR1_MII1_MR1_CLK)
AM437X_PRUETH1_RXD0: R447.2(P2) U11.D8(GPMC_A11/MCASP0_D1)
AM437X_PRUETH1_RXD1: R445.2(P2) U11.G8(GPMC_A10/MCASP0_D0)
AM437X_PRUETH1_RXD2: R443.2(P2) U11.B4(GPMC_A9/MCASP0_FSX)
AM437X_PRUETH1_RXD3: R441.2(P2) U11.F7(GPMC_A8/MCASP0_ACLKX)
AM437X_PRUETH1_RXDV: R459.1(P1) R461.2(P2) U11.C5(GPMC_A1/PR1_MII1_RXDV)
AM437X_PRUETH1_RXER: R136.2(P2) U11.B3(GPMC_WPN/PR1_MII1_RXER)
AM437X_PRUETH1_TXCLK: R141.2(P2) R241.2(P2) U11.E8(GPMC_A6/PR1_MII1_MT1_CLK)
AM437X_PRUETH1_TXD0: R469.2(P2) R471.2(P2) U11.E7(GPMC_A5/PR1_MII1_TXD0)
AM437X_PRUETH1_TXD1: R150.2(P2) R468.2(P2) U11.D7(GPMC_A4/PR1_MII1_TXD1)
AM437X_PRUETH1_TXD2: R153.2(P2) U11.A4(GPMC_A3/PR1_MII1_TXD2)
AM437X_PRUETH1_TXD3: R151.2(P2) U11.C6(GPMC_A2/PR1_MII1_TXD3)
AM437X_PRUETH1_TXEN: R155.2(P2) R157.1(P1) U11.C3(GPMC_A0/PR1_MII1_TXEN)
AM437X_PRUETH_MDCLK: R79.2(P2) R147.2(P2) U11.A12(GPMC_CLK/PR1_MDCLK)
AM437X_PRUETH_MDDATA: R78.2(P2) R146.2(P2) U11.D24(XDMA_EVENT_INTR0/PR1_MDIO)
AM437X_QSPI_CLK: R128.2(P2) U11.B12(GPMC_CSN3/QSPI_CLK)
AM437X_QSPI_CSN: R144.2(P2) U11.A8(GPMC_CSN0/QSPI_CSN)
AM437X_QSPI_D0: R137.2(P2) U11.A9(GPMC_ADVN_ALE/QSPI_D0)
AM437X_QSPI_D1: R449.2(P2) U11.E10(GPMC_OEN_REN/QSPI_D1)
AM437X_QSPI_D2: R457.2(P2) U11.D10(GPMC_WEN/QSPI_D2)
AM437X_QSPI_D3: R453.2(P2) U11.C10(GPMC_BE0N_CLE/QSPI_D3)
AM437X_RGMII1_RD0: R370.2(P2) U11.F17(MII1_RXD0/RGMII1_RD0)
AM437X_RGMII1_RD1: R368.2(P2) U11.B16(MII1_RXD1/RGMII1_RD1)
AM437X_RGMII1_RD2: R367.2(P2) U11.E16(MII1_RXD2/RGMII1_RD2)
AM437X_RGMII1_RD3: R365.2(P2) U11.C14(MII1_RXD3/RGMII1_RD3)
AM437X_RGMII1_RXCLK: R373.2(P2) U11.D13(MII1_RXCLK/RGMII1_RCLK)
AM437X_RGMII1_RXCTL: R371.2(P2) U11.A15(MII1_RXDV/RGMII1_RXCTL)
AM437X_RGMII1_TD0: R102.2(P2) U11.B15(MII1_TXD0/RGMII1_TD0)
AM437X_RGMII1_TD1: R107.2(P2) U11.A14(MII1_TXD1/RGMII1_TD1)
AM437X_RGMII1_TD2: R123.2(P2) U11.C13(MII1_TXD2/RGMII1_TD2)
AM437X_RGMII1_TD3: R439.2(P2) U11.C16(MII1_TXD3/RGMII1_TD3)
AM437X_RGMII1_TXCLK: R442.2(P2) U11.D14(MII1_TXCLK/RGMII1_TXCLK)
AM437X_RGMII1_TXCTL: R121.2(P2) U11.A13(MII1_TXEN/RGMII1_TXCTL)
AM437X_SD_CLKOUT: R263.2(P2) U11.AD25(CAM1_HSYNC/SD_DATA_IN0)
AM437X_SD_DATA_IN1: R262.2(P2) U11.AE21(CAM1_PCLK/SD_DATA_IN1)
AM437X_SPI0_CS0N: J16.30 R384.2(P2) U11.T20(SPI0_CS0)
AM437X_SPI0_D1: J16.28 R382.2(P2) U11.T21(SPI0_D1)
AM437X_SPI0_SCLK: R385.1(P1) U11.P23(SPI0_SCLK)
AM437X_SPI1_CS0: R99.2(P2) U11.A16(RMII1_REFCLK/SPI1_CS0N)
AM437X_SPI1_D1: R111.2(P2) U11.B13(MII1_RXERR/SPI1_D1)
AM437X_SPI1_SCLK: R437.2(P2) U11.D16(MII1_COL/SPI1_SCLK)
AM437X_UART0_CTSN: R72.1(P1) U11.L25(UART0_CTSN)
AM437X_UART0_RTSN: R71.1(P1) U11.J25(UART0_RTSN)
AM437X_UART0_RXD: R89.1(P1) U11.K25(UART0_RXD)
AM437X_UART0_TXD: R88.1(P1) R261.2(P2) U11.J24(UART0_TXD)
AM437X_VDDS: C199.1 C200.1 C210.1 C214.1 C216.1 R463.2(P2) U11.F20(VDDS#F20) U11.G6(VDDS#G6) U11.H12(VDDS#H12) U11.P19(VDDS#P19) U11.W15(VDDS#W15) U11.Y19(VDDS#Y19)
CAM0_GIO0: C151.1 R347.1(P1) R350.1(P1) U38.5(1A2)
CAM_MTR_EN: R343.1(P1) U6.22(O\E\) U11.A2(GPMC_WAIT0)
CAM_SRCCLK: U11.C24(XDMA_EVENT_INTR1/CLKOUT2) U38.4(1A1)
CAN0_RXDF: R248.2(P2) R386.2
CAN0_RXDF_PR1_EDC_LATCH0_IN: J16.41 R247.1(P1) R248.1(P1)
CAN0_TXDF: C177.1 R246.2(P2) R387.2
CAN0_TXDF_PR1_EDC_LATCH1_IN: J16.43 R245.1(P1) R246.1(P1)
CAP_VDD_RTC: C71.1 U11.AD3(CAP_VDD_RTC)
DDR_A0: R528.2(P2) U11.N1(DDR_A0) U20.N3(A0) U21.N3(A0)
DDR_A1: R218.2(P2) U11.L1(DDR_A1) U20.P7(A1) U21.P7(A1)
DDR_A2: R530.2(P2) U11.L2(DDR_A2) U20.P3(A2) U21.P3(A2)
DDR_A3: R535.2(P2) U11.P2(DDR_A3) U20.N2(A3) U21.N2(A3)
DDR_A4: R520.2(P2) U11.P1(DDR_A4) U20.P8(A4) U21.P8(A4)
DDR_A5: R533.2(P2) U11.R5(DDR_A5) U20.P2(A5) U21.P2(A5)
DDR_A6: R516.2(P2) U11.R4(DDR_A6) U20.R8(A6) U21.R8(A6)
DDR_A7: R534.2(P2) U11.R3(DDR_A7) U20.R2(A7) U21.R2(A7)
DDR_A8: R221.2(P2) U11.R2(DDR_A8) U20.T8(A8) U21.T8(A8)
DDR_A9: R217.2(P2) U11.R1(DDR_A9) U20.R3(A9) U21.R3(A9)
DDR_A10: R205.2(P2) U11.M6(DDR_A10) U20.L7(A10/AP) U21.L7(A10/AP)
DDR_A11: R219.2(P2) U11.T5(DDR_A11) U20.R7(A11) U21.R7(A11)
DDR_A12: R527.2(P2) U11.T4(DDR_A12) U20.N7(A12/B\C\) U21.N7(A12/B\C\)
DDR_A13: R216.2(P2) U11.N5(DDR_A13) U20.T3(A13) U21.T3(A13)
DDR_A14: R220.2(P2) U11.T3(DDR_A14) U20.T7(A14) U21.T7(A14)
DDR_BA0: R522.2(P2) U11.K1(DDR_BA0) U20.M2(BA0) U21.M2(BA0)
DDR_BA1: R206.2(P2) U11.K2(DDR_BA1) U20.N8(BA1) U21.N8(BA1)
DDR_BA2: R531.2(P2) U11.K3(DDR_BA2) U20.M3(BA2) U21.M3(BA2)
DDR_CASN: R532.2(P2) U11.N3(DDR_CASN) U20.K3(CASN) U21.K3(CASN)
DDR_CKE: R199.2(P2) R484.1(P1) U20.K9(CKE) U21.K9(CKE)
DDR_CKE0: R484.2(P2) U11.M3(DDR_CKE0)
DDR_CLK: R507.2(P2) U11.M2(DDR_CK) U20.J7(CK) U21.J7(CK)
DDR_CLKN: R508.2(P2) U11.M1(DDR_CKN) U20.K7(CKN) U21.K7(CKN)
DDR_CS0N: R521.2(P2) U11.M5(DDR_CSN0) U20.L2(CSN) U21.L2(CSN)
DDR_D0: U11.E3(DDR_D0) U20.E3(DQ0)
DDR_D1: U11.E2(DDR_D1) U20.F7(DQ1)
DDR_D2: U11.E1(DDR_D2) U20.F2(DQ2)
DDR_D3: U11.F3(DDR_D3) U20.F8(DQ3)
DDR_D4: U11.G4(DDR_D4) U20.H3(DQ4)
DDR_D5: U11.G3(DDR_D5) U20.H8(DQ5)
DDR_D6: U11.G2(DDR_D6) U20.G2(DQ6)
DDR_D7: U11.G1(DDR_D7) U20.H7(DQ7)
DDR_D8: U11.H1(DDR_D8) U20.D7(DQ8)
DDR_D9: U11.J6(DDR_D9) U20.C3(DQ9)
DDR_D10: U11.J5(DDR_D10) U20.C8(DQ10)
DDR_D11: U11.J4(DDR_D11) U20.C2(DQ11)
DDR_D12: U11.J3(DDR_D12) U20.A7(DQ12)
DDR_D13: U11.K6(DDR_D13) U20.A2(DQ13)
DDR_D14: U11.K5(DDR_D14) U20.B8(DQ14)
DDR_D15: U11.K4(DDR_D15) U20.A3(DQ15)
DDR_D16: U11.V5(DDR_D16) U21.E3(DQ0)
DDR_D17: U11.V4(DDR_D17) U21.F7(DQ1)
DDR_D18: U11.V3(DDR_D18) U21.F2(DQ2)
DDR_D19: U11.V2(DDR_D19) U21.F8(DQ3)
DDR_D20: U11.V1(DDR_D20) U21.H3(DQ4)
DDR_D21: U11.W4(DDR_D21) U21.H8(DQ5)
DDR_D22: U11.W5(DDR_D22) U21.G2(DQ6)
DDR_D23: U11.W6(DDR_D23) U21.H7(DQ7)
DDR_D24: U11.Y2(DDR_D24) U21.D7(DQ8)
DDR_D25: U11.Y3(DDR_D25) U21.C3(DQ9)
DDR_D26: U11.Y4(DDR_D26) U21.C8(DQ10)
DDR_D27: U11.AA3(DDR_D27) U21.C2(DQ11)
DDR_D28: U11.AB2(DDR_D28) U21.A7(DQ12)
DDR_D29: U11.AB1(DDR_D29) U21.A2(DQ13)
DDR_D30: U11.AC1(DDR_D30) U21.B8(DQ14)
DDR_D31: U11.AC2(DDR_D31) U21.A3(DQ15)
DDR_DQM0: U11.F4(DDR_DQM0) U20.E7(LDM)
DDR_DQM1: U11.H2(DDR_DQM1) U20.D3(UDM)
DDR_DQM2: U11.V6(DDR_DQM2) U21.E7(LDM)
DDR_DQM3: U11.Y1(DDR_DQM3) U21.D3(UDM)
DDR_DQS0: U11.F2(DDR_DQS0) U20.F3(LDQS)
DDR_DQS1: U11.J2(DDR_DQS1) U20.C7(UDQS)
DDR_DQS2: U11.W1(DDR_DQS2) U21.F3(LDQS)
DDR_DQS3: U11.AA1(DDR_DQS3) U21.C7(UDQS)
DDR_DQSN0: U11.F1(DDR_DQS0N) U20.G3(LDQSN)
DDR_DQSN1: U11.J1(DDR_DQS1N) U20.B7(UDQSN)
DDR_DQSN2: U11.W2(DDR_DQS2N) U21.G3(LDQSN)
DDR_DQSN3: U11.AA2(DDR_DQS3N) U21.B7(UDQSN)
DDR_ODT: R517.2(P2) U11.U1(DDR_ODT0) U20.K1(ODT) U21.K1(ODT)
DDR_RASN: R503.2(P2) U11.N2(DDR_RASN) U20.J3(RASN) U21.J3(RASN)
DDR_RESETN: U11.T1(DDR_RESETN) U20.T2(RESETN) U21.T2(RESETN)
DDR_WEN: R529.2(P2) U11.N4(DDR_WEN) U20.L3(WEN) U21.L3(WEN)
DRAIN0: D3.1(CATHODE) J1.19 U5.3(DRAIN0)
DRAIN1: D4.1(CATHODE) J1.20 U5.4(DRAIN1)
DRAIN2: D5.1(CATHODE) J1.21 U5.5(DRAIN2)
DRAIN3: D6.1(CATHODE) J1.22 U5.6(DRAIN3)
DRAIN4: D7.1(CATHODE) J1.23 U5.11(DRAIN4)
DRAIN5: D8.1(CATHODE) J1.24 U5.12(DRAIN5)
DRAIN6: D9.1(CATHODE) J1.25 U5.13(DRAIN6)
DRAIN7: D10.1(CATHODE) J1.26 U5.14(DRAIN7)
EECS: U13.63(EECS) U16.1(CS)
EEDATA: R180.1(P1) U13.61(EEDATA) U16.3(DI)
EESK: U13.62(EESK) U16.2(CLK)
EHRPWM3_SYNCO: J16.23 R253.1(P1)
EMU2: J7.17(EMU2) TP4.1
EMU3: J7.18(EMU3) TP6.1
EMU4: J7.19(EMU4) TP5.1
EMU_RSTN: C174.1 J7.15(SRST) R389.1(P1)
EMU_USB_DM: J18.2(DM) U13.7(DM) U47.5(IO2)
EMU_USB_DP: J18.3(DP) U13.8(DP) U47.3(IO1)
ENDAT_EN: R388.2(P2) R519.1(P1) U57.2(R\E\)
EQEP1_INDEX: J16.51 R241.1(P1)
EQEP1_STROBE: J16.53 R465.1(P1)
EQEP1A_IN: J16.57 R468.1(P1)
EQEP1B_IN: J16.55 R471.1(P1)
EQEP2_INDEX: J16.42 U11.B11(GPMC_AD14/EQEP2_INDEX)
EQEP2_STROBE: J16.44 U11.A11(GPMC_AD15/EQEP2_STROBE)
EQEP2A_IN: J16.46 U11.E11(GPMC_AD12/EQEP2A_IN)
EQEP2B_IN: J16.48 U11.C11(GPMC_AD13/EQEP2B_IN)
ETH1_LDO_O: Q9.G(GATE) U37.43(LDO_O)
ETH1_MDC: R374.1(P1) U37.36(MDC)
ETH1_MDIO: R357.1(P1) U37.37(MDIO)
ETH1_RESETN: C161.1 D20.2(ANODE) R361.1(P1) U37.42(RESET_N) U42.4(Y)
ETH1_RXCLK: R372.2(P2) R373.1(P1) R400.2(P2) U37.35(RX_CLK)
ETH1_RXD0: R370.1(P1) R396.2(P2) R397.2(P2) U37.32(RXD0)
ETH1_RXD1: R368.1(P1) R369.2(P2) R395.2(P2) U37.31(RXD1)
ETH1_RXD2: R367.1(P1) R393.2(P2) R394.2(P2) U37.28(RXD2)
ETH1_RXD3: R365.1(P1) R366.2(P2) R392.2(P2) U37.27(RXD3)
ETH1_RXDV: R371.1(P1) R398.2(P2) R399.2(P2) U37.33(RX_DV)
ETH1_TXCLK: R442.1(P1) U37.24(GTX_CLK)
ETH1_TXD0: R102.1(P1) U37.19(TXD0)
ETH1_TXD1: R107.1(P1) U37.20(TXD1)
ETH1_TXD2: R123.1(P1) U37.21(TXD2)
ETH1_TXD3: R439.1(P1) U37.22(TXD3)
ETH1_TXEN: R121.1(P1) U37.25(TX_EN)
ETH1GB_25MHZCLK: R323.2 U37.46(XI)
ETH_MDIO_CLK: R374.2(P2) U11.B17(MDIO_CLK/MDIO_CLK)
ETH_MDIO_DATA: R66.1(P1) R357.2(P2) U11.A17(MDIO_DATA/MDIO_DATA)
ETHER1_D0N: J4.10 U37.3(TXRXM_A)
ETHER1_D0P: J4.9 U37.2(TXRXP_A)
ETHER1_D1N: J4.8 U37.6(TXRXM_B)
ETHER1_D1P: J4.7 U37.5(TXRXP_B)
ETHER1_D2N: J4.6 U37.8(TXRXM_C)
ETHER1_D2P: J4.5 U37.7(TXRXP_C)
ETHER1_D3N: J4.4 U37.11(TXRXM_D)
ETHER1_D3P: J4.3 U37.10(TXRXP_D)
F_ADBUS0: R133.2(P2) U13.16(ADBUS0)
F_ADBUS1: R120.2(P2) U13.17(ADBUS1)
F_ADBUS2: R119.2(P2) U13.18(ADBUS2)
F_ADBUS3: R118.2(P2) U13.19(ADBUS3)
F_ADBUS4: R117.2(P2) U13.21(ADBUS4)
F_ADBUS5: R115.2(P2) U13.26(ACBUS0)
F_ADBUS6: R116.2(P2) U13.23(ADBUS6)
F_ADBUS7: R113.2(P2) U13.30(ACBUS4)
FT_SRESET: R115.1(P1) R160.2(P2) U50.1(A)
FT_SRESETB: R489.2(P2) U51.4(Y)
FT_SRESETN: U50.4(Y) U51.2(A)
FT_VBUS: R170.1(P1) U50.2(B)
FTDI_REF: R460.1(P1) U13.6(REF)
FTDI_VPHY: C250.2 C251.2 FB16.1 U13.4(VPHY)
FTDI_VPLL: C245.2 C246.2 FB15.1 U13.9(VPLL)
GP_I2C_SCL: R22.2(P2) R425.1(P1) U31.8(B1) U32.6(SCL)
GP_I2C_SDA: R21.2(P2) R419.1(P1) U31.1(B2) U32.5(SDA)
HDQ: J16.50 R243.2(P2)
IDC_SENSE: C325.1 R109.1(P1) R207.1(P1) R518.2(P2)
IND_I2C_SCL: J16.27 R430.1(P1)
IND_I2C_SDA: J16.29 R432.1(P1)
INDUS_INPUT0: J1.1 R295.1(P1)
INDUS_INPUT1: J1.3 R294.1(P1)
INDUS_INPUT2: J1.5 R293.1(P1)
INDUS_INPUT3: J1.7 R292.1(P1)
INDUS_INPUT4: J1.9 R291.1(P1)
INDUS_INPUT5: J1.11 R290.1(P1)
INDUS_INPUT6: J1.13 R289.1(P1)
INDUS_INPUT7: J1.15 R288.1(P1)
INDUS_INPUTCLK: R437.1(P1) U4.25(CLK)
INDUS_INPUTCSN: R99.1(P1) U4.24(C\E\)
INDUS_INPUTLDN: R105.1(P1) U4.26(L\D\)
INDUS_INPUTSO: U4.23(SOP) U36.2(A)
IS_IHB1: C309.1 R440.2(P2) R501.1(P1) R509.2(P2) U11.Y12(ADC0_AIN1)
IS_IHB2: C84.1 R185.2(P2) R189.1(P1) R436.2(P2) U11.AA13(ADC0_AIN3)
IS_IHB3: C333.1 R103.2(P2) R523.1(P1) R539.2(P2) U11.AC13(ADC0_AIN5)
IS_MIHB1: C286.1 R497.1(P1) U11.Y15(ADC1_AIN5)
IS_MIHB2: C83.1 R188.1(P1) U11.AB16(ADC1_AIN1)
IS_MIHB3: C334.1 R524.1(P1) U11.AB15(ADC1_AIN3)
JTAG_EMU0: J7.13(EMU0) R376.1(P1) R402.1(P1) U11.N23(JTAG_EMU0)
JTAG_EMU1: J7.14(EMU1) R381.1(P1) R403.1(P1) U11.T24(JTAG_EMU1)
JTAG_TCK: R407.2(P2) R413.2(P2) U11.AA25(JTAG_TCK) U45.13(1B1)
JTAG_TDI: J7.3(TDI) U11.Y20(JTAG_TDI) U45.12(1B2)
JTAG_TDO: J7.7(TDO) U11.AA24(JTAG_TDO) U49.2(A1)
JTAG_TMS: J7.1(TMS) U11.Y24(JTAG_TMS) U45.11(2B1)
JTAG_TRSTN: J7.2(TRSTN) R433.2(P2) U11.Y25(JTAG_TRSTN) U45.10(2B2)
JTAGPOD_DET: R421.1(P1) U8.4(Y)
MMC_CD: J19.10(CD) R84.1(P1) R548.1(P1) U59.3(IO1)
MMC_CLK: J19.5(CLOCK) R179.1(P1) U27.1(IO1)
MMC_CMD: J19.3(CMD) R177.1(P1) R244.1(P1) U27.7(IO5)
MMC_D0: J19.7(DAT0) R174.1(P1) R267.1(P1) U27.2(IO2)
MMC_D1: J19.8(DAT1) R167.1(P1) R266.1(P1) U27.3(IO3)
MMC_D2: J19.1(DAT2) R161.1(P1) R236.1(P1) U27.6(IO4)
MMC_D3: J19.2(CD/DAT3) R158.1(P1) R231.1(P1) U27.8(IO6)
MOT1_ADC: R435.2(P2) R561.2(P2) U11.Y13(ADC0_AIN2)
MOT1_LEVEL: C349.1 R554.2(P2) R561.1(P1) R562.1(P1)
MOT2_ADC: R129.2(P2) R563.2(P2) U11.AD13(ADC0_AIN6)
MOT2_LEVEL: C350.1 R555.2(P2) R563.1(P1) R564.1(P1)
MOT3_ADC: R124.2(P2) R558.2(P2) U11.AE13(ADC0_AIN7)
MOT3_LEVEL: C348.1 R553.2(P2) R558.1(P1) R559.1(P1)
MOT_OUT1: L2.1 U23.5(OUT1)
MOT_OUT2: L3.1 U23.8(OUT2)
MOT_OUT3: L1.1 U23.9(OUT3)
MOT_PGND1: C308.1 R195.2(P2) R538.1 U23.6(PGND1)
MOT_PGND2: C300.1 R193.2(P2) R537.1 U23.7(PGND2)
MOT_PGND3: C332.1 R211.2(P2) R536.1 U23.10(PGND3)
MOT_PGNDTOTAL: C300.2 C308.2 C321.1 C332.2 R200.2(P2) R203.2(P2) R209.2(P2) R215.1(P1) R222.2(P2) R536.2 R537.2 R538.2 R543.2(P2)
MOTOR_OUT1: J17.1 L2.2 R562.2(P2)
MOTOR_OUT2: J17.2 L3.2 R564.2(P2)
MOTOR_OUT3: J17.3 L1.2 R559.2(P2)
MOTVM_ADC: C68.1 R154.1(P1) R454.1(P1) R476.2(P2)
MTR_FAULT: Q10.G(GATE) R60.2(P2) R61.2(P2) R62.2(P2) R186.1(P1) R245.2(P2) R495.2(P2) U11.F11(GPMC_AD10/GPIO) U23.18(F\A\U\L\T\)
MTRA_GND: C270.2 J10.1 J10.5 R513.1(P1)
OSC0_IN: C36.1 R82.2(P2) R92.2(P2) Y1.3
OSC0_OUT: C35.1 R82.1(P1) R91.2(P2) Y1.1
PHY1_LED_ACTN: R53.2(P2) R270.1 R345.2(P2) U37.17(LED1 / PME_N1)
PHY1_LED_LINKN: R45.2(P2) R269.1 R336.2(P2) U37.15(LED2)
PORZ_RELEASE: R487.1(P1) U26.16(R\E\S\E\T\2\)
PORZN: R75.1(P1) R90.2(P2) R416.2(P2) R487.2(P2) U48.2(A) U54.2(A)
PR1_EDC_SYNC0_OUT: J16.18 R72.2(P2)
PR1_EDC_SYNC1_OUT: R71.2(P2) R256.1(P1)
PR1_EDIO_DATA6: J3.6 U11.B9(GPMC_CSN1/PR1_EDIO_DATA6)
PR1_EDIO_DATA7: J3.8 U11.F10(GPMC_CSN2/PR1_EDIO_DATA7)
PRU0_ENDAT0_CLK: J16.31 R422.1(P1) R428.1(P1) R493.2(P2)
PRU0_ENDAT0_OUT: J16.33 R423.1(P1) R427.1(P1) R540.2(P2)
PRU0_ENDAT1_CLK: J16.32 R252.2(P2)
PRU0_ENDAT1_IN: J16.38 R249.2(P2)
PRU0_ENDAT1_OUT: J16.34 R251.2(P2)
PRU0_ENDAT1_OUTEN: J16.36 R250.2(P2)
PRU0_ENDAT2_CLK: J16.52 R242.2(P2)
PRU0_ENDAT2_IN: J16.58 R238.2(P2)
PRU0_ENDAT2_OUT: J16.54 R240.2(P2)
PRU0_ENDAT2_OUTEN: J16.56 R239.2(P2)
PRUETH0_25MHZCLK: R311.2 U7.23(XI)
PRUETH0_COL: R57.2(P2) R351.1(P1) R352.2(P2) R434.1(P1) U7.29(COL)
PRUETH0_CRS: R65.1(P1) U7.27(CRS)
PRUETH0_INT: TP3.1 U7.8(PWRDNN/INTN)
PRUETH0_LINKLED: R77.1(P1) R348.2(P2) U7.17(LED_LINK)
PRUETH0_MDC: R79.1(P1) U7.20(MDC)
PRUETH0_MDIO: R78.1(P1) U7.19(MDIO)
PRUETH0_RESETN: U7.18(RESET_N) U43.4(Y)
PRUETH0_RXCLK: R76.1(P1) U7.25(RX_CLK)
PRUETH0_RXD0: R55.2(P2) R349.1(P1) U7.30(RXD_0)
PRUETH0_RXD1: R51.2(P2) R344.1(P1) U7.31(RXD_1)
PRUETH0_RXD2: R46.2(P2) R339.1(P1) U7.32(RXD_2)
PRUETH0_RXD3: R44.2(P2) R337.1(P1) U7.1(RXD_3)
PRUETH0_RXDV: R67.1(P1) U7.26(RX_DV)
PRUETH0_RXERR: R59.1(P1) U7.28(RX_ERR)
PRUETH0_TXCLK: R410.1(P1) U7.2(TX_CLK)
PRUETH0_TXD0: R391.1(P1) U7.4(TXD_0)
PRUETH0_TXD1: R378.1(P1) U7.5(TXD_1)
PRUETH0_TXD2: R377.1(P1) U7.6(TXD_2)
PRUETH0_TXD3: R390.1(P1) U7.7(TXD_3)
PRUETH0_TXEN: R405.1(P1) U7.3(TX_EN)
PRUETH1_25MHZCLK: R312.2 U12.23(XI)
PRUETH1_COL: R85.1(P1) R134.2(P2) R452.2(P2) R455.1(P1) R473.1(P1) U12.29(COL)
PRUETH1_CRS: R140.1(P1) U12.27(CRS)
PRUETH1_INT: TP8.1 U12.8(PWRDNN/INTN)
PRUETH1_LINKLED: R145.1(P1) R448.2(P2) U12.17(LED_LINK)
PRUETH1_MDC: R147.1(P1) U12.20(MDC)
PRUETH1_MDIO: R146.1(P1) R462.1(P1) U12.19(MDIO)
PRUETH1_RESETN: U12.18(RESET_N) U44.4(Y)
PRUETH1_RXCLK: R466.1(P1) U12.25(RX_CLK)
PRUETH1_RXD0: R130.2(P2) R447.1(P1) U12.30(RXD_0)
PRUETH1_RXD1: R127.2(P2) R445.1(P1) U12.31(RXD_1)
PRUETH1_RXD2: R122.2(P2) R443.1(P1) U12.32(RXD_2)
PRUETH1_RXD3: R108.2(P2) R441.1(P1) U12.1(RXD_3)
PRUETH1_RXDV: R461.1(P1) U12.26(RX_DV)
PRUETH1_RXERR: R136.1(P1) U12.28(RX_ERR)
PRUETH1_TXCLK: R141.1(P1) U12.2(TX_CLK)
PRUETH1_TXD0: R469.1(P1) U12.4(TXD_0)
PRUETH1_TXD1: R150.1(P1) U12.5(TXD_1)
PRUETH1_TXD2: R153.1(P1) U12.6(TXD_2)
PRUETH1_TXD3: R151.1(P1) U12.7(TXD_3)
PRUETH1_TXEN: R155.1(P1) U12.3(TX_EN)
PRUETHER0_RDN: J6.2 R31.2(P2) U7.9(RD-)
PRUETHER0_RDP: J6.1 R43.2(P2) U7.10(RD+)
PRUETHER0_TDN: J6.6 R50.2(P2) U7.11(TD-)
PRUETHER0_TDP: J6.5 R56.2(P2) U7.12(TD+)
PRUETHER1_RDN: J9.6 R101.2(P2) U12.9(RD-)
PRUETHER1_RDP: J9.5 R106.2(P2) U12.10(RD+)
PRUETHER1_TDN: J9.2 R125.2(P2) U12.11(TD-)
PRUETHER1_TDP: J9.1 R131.2(P2) U12.12(TD+)
RT_MII0_RXDV: J3.3 R63.1(P1)
RT_MII0_TXEN: J3.1 R404.1(P1)
RT_MII1_RXDV: J3.4 R459.2(P2)
RT_MII1_TXEN: J3.2 R157.2(P2)
RT_MII_EDIO_DATA0: J3.5 R382.1(P1)
RT_MII_EDIO_DATA1: J3.7 R384.1(P1)
RTCK: J7.9(TCKRTN) R413.1(P1)
SD0_CLKIN: J16.3 R265.1(P1)
SD_CLKIN: J16.5 R264.1(P1)
SD_DATA_IN0_SD_CLKOUT: J16.7 R263.1(P1)
SD_DATA_IN1: J16.9 R262.1(P1)
SD_DATA_IN2: J16.11 R261.1(P1)
SD_DATA_IN3: J16.13 R260.1(P1)
SD_DATA_IN4: J16.15 R259.1(P1)
SD_DATA_IN5_PR1_EDC_LATCH0_IN: J16.17 R258.1(P1)
SD_DATA_IN6: J16.19 R255.1(P1)
SD_DATA_IN7: J16.21 R254.1(P1)
SENSOR_HREF: J5.8 U38.10(2B2)
SENSOR_PCLK: J5.13 U34.4(B)
SENSOR_PWRDN: J5.11 R304.2(P2) R305.1(P1)
SENSOR_RESET: J5.15 U38.12(1B2)
SENSOR_SIO_C: J5.4 R15.1(P1) U31.5(A1)
SENSOR_SIO_D: J5.2 R16.1(P1) U31.4(A2)
SENSOR_VSYNC: J5.6 U38.11(2B1)
SENSOR_XCLK: J5.10 U38.13(1B1)
SENSOR_Y2: J5.24 U6.21(B1)
SENSOR_Y3: J5.23 U6.20(B2)
SENSOR_Y4: J5.22 U6.19(B3)
SENSOR_Y5: J5.21 U6.18(B4)
SENSOR_Y6: J5.20 U6.17(B5)
SENSOR_Y7: J5.19 U6.16(B6)
SENSOR_Y8: J5.18 U6.15(B7)
SENSOR_Y9: J5.17 U6.14(B8)
SPI0_DIN: J16.26 U11.T22(SPI0_D0)
SPI0_SCLK: J16.24 R385.2(P2)
SPIMEM_CLK: R128.1(P1) U46.16(SCLK)
SPIMEM_CS: R144.1(P1) U46.7(C\S\)
SPIMEM_D0: R137.1(P1) U46.15(SI/SIO0)
SPIMEM_D1: R449.1(P1) U46.8(SO/SIO1)
SPIMEM_D2: R457.1(P1) R458.1(P1) U46.9(W\P\/SIO2)
SPIMEM_D3: R453.1(P1) U46.1(DNU/SIO3)
SYNCI: R257.1(P1) U11.R24(SPI4_D0)
SYS_RESETN: J16.25 R152.2(P2) R389.2(P2) R499.1(P1) U42.2(A) U43.2(B) U44.2(B)
SYS_WARMRESETN: C287.1 R69.1(P1) R86.2(P2) R489.1(P1) R498.1(P1) R499.2(P2) U54.4(Y)
SYSBOOT0: R26.1(P1) R318.2(P2) U9.17(2A4)
SYSBOOT1: R25.1(P1) R319.2(P2) U9.15(2A3)
SYSBOOT2: R24.1(P1) R320.2(P2) U9.13(2A2)
SYSBOOT3: R23.1(P1) R321.2(P2) U9.11(2A1)
SYSBOOT4: R30.1(P1) R314.2(P2) U9.8(1A4)
SYSBOOT5: R29.1(P1) R315.2(P2) U9.6(1A3)
SYSBOOT6: R28.1(P1) R316.2(P2) U9.4(1A2)
SYSBOOT7: R27.1(P1) R317.2(P2) U9.2(1A1)
SYSBOOT8: R39.1(P1) R331.2(P2) U39.17(2A4)
SYSBOOT9: R40.1(P1) R330.2(P2) U39.15(2A3)
SYSBOOT10: R41.1(P1) R329.2(P2) U39.13(2A2)
SYSBOOT11: R42.1(P1) R328.2(P2) U39.11(2A1)
SYSBOOT12: R35.1(P1) R335.2(P2) U39.8(1A4)
SYSBOOT13: R36.1(P1) R334.2(P2) U39.6(1A3)
SYSBOOT14: R37.1(P1) R333.2(P2) U39.4(1A2)
SYSBOOT15: R38.1(P1) R332.2(P2) U39.2(1A1)
TCK: J7.11(TCK) R407.1(P1)
UARTX_RXD: R89.2(P2) U13.38(BDBUS0)
UARTX_TXD: R88.2(P2) U13.39(BDBUS1)
USBJTAG_ENN: R421.2(P2) U41.4(O\E\) U45.14(2O\E\) U45.15(1O\E\) U49.4(O\E\)
VADD33_PRUETH0: C33.1 R346.2(P2) U7.14(AVDD33)
VADD33_PRUETH1: C58.1 R446.2(P2) U12.14(AVDD33)
VAM437X_DDR_VREF: C238.1 C247.2 R470.2 R474.1 U11.T6(DDR_VREF)
VENDAT: C270.1 J10.2 J10.8 R483.2(P2) R485.2(P2)
VETH1_AVDDH: C50.1 C142.1 C182.1 FB5.2 Q9.S(SOURCE) U37.1(AVDDH#1) U37.12(AVDDH#12) U37.47(AVDDH#47)
VETH1_AVDDL: C21.1 C143.1 FB2.2 U37.4(AVDDL#4) U37.9(AVDDL#9)
VETH1_AVDDL_PLL: C22.1 C26.1 C152.1 FB3.2 U37.44(AVDDL_PLL)
VETH1_AVDDL_PMOS: C49.1 FB2.1 FB3.1 FB4.1 Q9.D1(DRAIN1) Q9.D2(DRAIN2)
VETH1_DVDDH: C43.1 C149.1 C187.1 D20.1(CATHODE) R66.2(P2) R336.1(P1) R345.1(P1) R353.2(P2) R361.2(P2) R392.1(P1) R393.1(P1) R395.1(P1) R396.1(P1) R399.1(P1) R400.1(P1) R401.1(P1) U37.16(DVDDH#16) U37.34(DVDDH#34) U37.40(DVDDH#40) U42.5(VCC)
VETH1_DVDDL: C28.1 C162.1 FB4.2 U37.14(DVDDL#14) U37.18(DVDDL#18) U37.23(DVDDL#23) U37.26(DVDDL#26) U37.30(DVDDL#30) U37.39(DVDDL#39)
VMTR_PWRIN: D17.2(ANODE) J14.1
VPWRIN_JCK: D19.2(ANODE) J12.1 J13.1
VPWRIN_PREFUSE: D19.1(CATHODE) F1.1
VUSB_FTDI: C225.1 D12.2(ANODE) FB13.2 R168.2(P2)
VUSB_JTAG: C226.1 FB13.1 J18.1(VBUS) U47.1(VCC)
XTIN: C261.1 U13.2(XTIN) Y4.1
XTOUT: C255.1 U13.3(XTOUT) Y4.2
N10692191: R498.2(P2) SW2.3 SW2.4
N11217419: C306.1 R507.1(P1) R508.1(P1)
N11219802: R232.1(P1) U25.7(EN)
N11219922: R233.1(P1) U25.9(PGOOD)
N11219986: C108.1 R225.1(P1) U25.5(VOSNS)
N11220684: C109.1 R226.1(P1) R549.2(P2) U25.1(REFIN)
N11290828: R87.1(P1) U11.G25(NMIN)
N11290910: R86.1(P1) U11.G22(RESETIN_OUTN)
N11291034: R90.1(P1) U11.Y23(PORZN)
N12081710: J8.1 R353.1(P1) U37.38(INT_N / PME_N2)
N12123192: J4.11 R270.2
N12123204: J4.14 R269.2
N12138943: R32.1 U37.48(ISET)
N12139138: TP18.1 U37.41(CLK125_NDO)
N12220066: C38.1 C163.1 C164.1 C167.1 U7.13(PFBIN1) U7.15(PFBOUT) U7.24(PFBIN2)
N12225140: J9.11 R420.1(P1)
N12225158: C65.1 C232.1 C237.1 C244.1 U12.13(PFBIN1) U12.15(PFBOUT) U12.24(PFBIN2)
N12225278: J9.10 R134.1(P1)
N12225708: R473.2(P2) U11.A3(GPMC_BE1N/PR1_MII1_COL)
N12225872: R85.2(P2) U11.E24(PRINT_ON/PR1_MII1_RXLINK)
N12226470: J9.9 R475.1(P1)
N12226600: R431.1(P1) U44.1(A)
N12591797: TP2.1 U11.H20(CLKREQ)
N12595082: R162.2(P2) U11.AC3(DDR_VTP)
N12745256: Q8.G(GATE) R9.2(P2) R10.1(P1)
N12745282: Q8.D(DRAIN) R272.1(P1)
N12745290: R272.2(P2) U1.2(R)
N12745520: Q6.G(GATE) R7.2(P2) R8.2(P2)
N12745536: Q6.D(DRAIN) R268.1(P1)
N12745804: Q7.G(GATE) R11.2(P2) R12.2(P2)
N12745812: R271.2(P2) U1.4(Y)
N12745820: Q7.D(DRAIN) R271.1(P1)
N12825337: J10.7 U55.6(A)
N12825341: J10.6 U55.7(B)
N12825345: R493.1(P1) U55.4(D)
N12825349: TP12.1 U55.1(R)
N12825453: J10.4 R512.1(P1) U57.7(B)
N12825465: J10.3 R512.2(P2) U57.6(A)
N12825469: R514.1(P1) U57.1(R)
N12825473: R540.1(P1) U57.4(D)
N12825749: R526.1(P1) U57.3(DE)
N12957779: R114.2(P2) U13.28(ACBUS2)
N12957783: R114.1(P1) U49.6(B2)
N12957791: R112.2(P2) U13.32(ACBUS5)
N12957851: R168.1(P1) R169.2(P2) R170.2(P2) U13.59(BCBUS7)
N12957949: R113.1(P1) U41.3(A2)
N12958009: R135.1(P1) U13.14(RESET#)
N12958129: D12.1(CATHODE) R171.2
N12958219: R178.1(P1) R180.2(P2) U16.4(DO)
N12958339: TP10.1 U13.36(SUSPEND#)
N12958347: R171.1 U13.60(PWREN#)
N12958931: R116.1(P1) U41.2(A1)
N12958935: R117.1(P1) U45.7(2A2)
N12958939: R118.1(P1) U45.6(2A1)
N14606304: R504.2(P2) U20.L8(ZQ)
N14617357: R198.2(P2) U21.L8(ZQ)
N14814629: C212.1 U11.E13(CAP_VDD_SRAM_CORE)
N14814645: C218.1 U11.E14(CAP_VDD_SRAM_MPU)
N14814653: C191.1 U11.F19(CAP_VBB_MPU)
N14814919: C29.1 C30.1 FB8.2 U11.U21(VDDA1P8V_USB1) U11.W21(VDDA1P8V_USB0)
N15803440: R172.2(P2) U11.AE2(ENZ_KALDO_1P8V)
N15803446: R143.2(P2) U11.AD6(PMIC_POWER_EN0)
N15803450: R467.1(P1) U11.AE4(OSC1_OUT)
N15803452: C248.1 R467.2(P2) Y3.4
N15803458: C243.1 U11.AE5(OSC1_IN) Y3.1
N15803478: R148.2(P2) U11.AE6(RTC_PORZ)
N15803480: R163.2(P2) U11.AE3(EXT_WAKEUP0)
N15803482: R148.1(P1) R479.1(P1) U48.4(Y)
N15803502: R163.1(P1) TP13.1
N15838226: C14.1 C136.1 J5.9 R313.1(P1)
N15840029: C125.1 U30.4(NR)
N15840733: R297.1(P1) U31.6(OE)
N15910922: R140.2(P2) U11.F23(PRINT_MB/PR1_MII1_CRS)
N15911835: R464.2(P2) U12.16(RBIAS)
N15980233: C94.1 U23.1(CP1)
N15980235: C94.2 U23.2(CP2)
N15980277: C100.1 R213.2(P2) R214.1 U23.13(COMPN)
N15980287: R186.2(P2) R496.2(P2) U23.19(COMPON)
N15980309: R215.2(P2) U23.12(COMPP)
N15980493: D15.2(ANODE) R183.1
N15980497: Q10.D(DRAIN) R183.2
N15980559: R83.2(P2) U23.17(S\L\E\E\P\N\)
N16086432: R324.1(P1) U35.B2(EN)
N16086456: R356.1(P1) U35.D3(SCL)
N16086460: R354.1(P1) U35.D2(SDA)
N16086926: R325.1(P1) U35.A3(VSEL1)
N16086934: R355.1(P1) U35.C2(VSEL0)
N16087451: C1.1 U3.1(BOOT)
N16087466: C1.2 D1.1(CATHODE) L4.1 U3.8(LX)
N16087487: R18.2(P2) U3.3(ROSC)
N16087773: C17.1 U3.4(SS)
N16088130: R14.2(P2) U3.6(COMP)
N16088430: R19.1 R298.1(P1) U3.5(VSNS)
N16094628: J7.4(TDIS) R429.2(P2)
N16169613: R546.1(P1) U58.16(B6)
N16169629: J15.5 U58.18(B4)
N16169633: R547.1(P1) U58.17(B5)
N16169657: C347.1 J15.2 R552.1(P1) U58.21(B1)
N16169661: C351.1 J15.3 R560.1(P1) U58.20(B2)
N16169665: C352.1 J15.4 R565.1(P1) U58.19(B3)
N16251668: R97.1(P1) U5.15(SCL)
N16251678: R98.1(P1) U5.2(SDA)
N16279225: C179.1 C180.1 C198.1 C206.1 C242.1 FB10.2 U11.E17(VDDS_PLL_MPU) U11.F13(VDDS_SRAM_CORE_BG) U11.F14(VDDS_SRAM_MPU_BB) U11.G5(VDDS_PLL_DDR) U11.N21(VDDS_PLL_CORE_LCD)
N16281493: TP19.1 U11.H21(TESTOUT)
N16283418: C11.1 R14.1(P1)
N16286128: C51.2 D11.1(CATHODE) L6.1 U10.8(LX)
N16286350: C51.1 U10.1(BOOT)
N16286370: R94.2(P2) U10.3(ROSC)
N16286398: C44.1 U10.4(SS)
N16286420: R95.1 U10.6(COMP)
N16286444: R93.1 R409.1 U10.5(VSNS)
N16286506: C46.1 R95.2
N16287061: C67.2 D13.1(CATHODE) L8.1 U15.8(LX)
N16287283: C67.1 U15.1(BOOT)
N16287303: R175.2(P2) U15.3(ROSC)
N16287331: C77.1 U15.4(SS)
N16287353: R173.2(P2) U15.6(COMP)
N16287439: C75.1 R173.1(P1)
N16288012: C88.2 D16.1(CATHODE) L9.1 U17.8(LX)
N16288234: C88.1 U17.1(BOOT)
N16288254: R182.2(P2) U17.3(ROSC)
N16288282: C79.1 U17.4(SS)
N16288304: R184.2(P2) U17.6(COMP)
N16288328: R181.2(P2) R491.1(P1) U17.5(VSNS)
N16288390: C82.1 R184.1(P1)
N16700927: J9.12 R448.1(P1)
N16702915: R326.1(P1) U6.3(A1)
N16702921: R327.1(P1) U6.4(A2)
N16738182: R176.2(P2) R481.1(P1) U15.5(VSNS)
N16738683: R486.2(P2) U52.A1(VOUT#A1) U52.B1(VOUT#B1)
N16738880: R490.1(P1) U52.C2(ON)
N16739248: R488.2(P2) U53.A1(VOUT#A1) U53.B1(VOUT#B1)
N16739276: R482.1(P1) U53.C2(ON)
N16740119: R379.2(P2) U40.A1(VOUT#A1) U40.B1(VOUT#B1)
N16740147: R359.1(P1) R360.1(P1) U40.C2(ON)
N16740391: R224.1(P1) U26.1(M\R\)
N16743008: C343.1 U26.2(CT4)
N16743015: C344.1 U26.3(CT3)
N16743022: C345.1 U26.4(CT2)
N16743029: C346.1 U26.5(CT1)
N16744367: R230.1(P1) R556.2(P2) U26.9(SENSE2)
N16744371: R229.1(P1) R551.2(P2) U26.8(SENSE3)
N16744375: R227.1(P1) R550.2(P2) U26.7(SENSE4L)
N16744379: R235.2 R557.2(P2) U26.10(SENSE1)
N16782266: C173.1 FB9.2 U11.E23(VDDS_CLKOUT)
N16818596: J6.9 R411.1(P1)
N16818719: R412.1(P1) R417.1(P1) U43.1(A)
N16819128: R362.2(P2) U7.16(RBIAS)
N16839102: C23.1 R338.1(P1) U4.14(VCC)
N16839202: R322.2(P2) U4.13(RLIM)
N16839209: R34.2(P2) U4.2(DB1)
N16839216: R33.2(P2) U4.1(DB0)
N16844891: D4.2(ANODE) R286.2(P2)
N16844892: D9.2(ANODE) R281.2(P2)
N16844893: D10.2(ANODE) R280.2(P2)
N16844894: D7.2(ANODE) R283.2(P2)
N16844899: D8.2(ANODE) R282.2(P2)
N16844909: D3.2(ANODE) R287.2(P2)
N16844924: D6.2(ANODE) R284.2(P2)
N16844930: D5.2(ANODE) R285.2(P2)
N16880569: R416.1(P1) U9.1(1OE#) U9.19(2OE#) U39.1(1OE#) U39.19(2OE#)
N16898152: R298.2(P2) R302.1(P1)
N16899204: R409.2 R415.1(P1)
N16899853: R480.1(P1) R481.2(P2)
N16900690: R491.2(P2) R492.1(P1)
N17007255: R54.1(P1) R111.1(P1) U36.4(Y)
N17015946: D22.1(CATHODE) J14.2
N17047964: R515.1(P1) U58.2(DIR)
N17047991: R541.1(P1) R542.1(P1) U58.22(O\E\)
N17048274: R544.1(P1) U58.14(B8)
N17048276: R545.1(P1) U58.15(B7)
N17049952: C253.2 D14.1(CATHODE) L7.1 U14.8(LX)
N17050053: R165.1 R166.2(P2) U14.5(VSNS)
N17050067: R164.1(P1) R165.2
N17050085: C253.1 U14.1(BOOT)
N17050095: R156.2(P2) U14.3(ROSC)
N17050109: C69.1 U14.4(SS)
N17050128: R159.2(P2) U14.6(COMP)
N17050161: C72.1 R159.1(P1)
N17074741: J6.10 R352.1(P1)
N17080008: R406.2(P2) U9.16(1Y2)
N17080011: R408.2(P2) U9.18(1Y1)
N17084990: R268.2(P2) U1.3(G)
N17085264: Q3.G(GATE) R278.2(P2) R279.1(P1)
N17085270: Q3.D(DRAIN) R5.1(P1)
N17085272: R5.2(P2) U2.2(R)
N17085280: Q5.G(GATE) R274.2(P2) R275.2(P2)
N17085284: Q5.D(DRAIN) R4.1(P1)
N17085292: Q4.G(GATE) R276.2(P2) R277.2(P2)
N17085296: R6.2(P2) U2.4(Y)
N17085298: Q4.D(DRAIN) R6.1(P1)
N17085459: R4.2(P2) U2.3(G)
N17134629: R299.2(P2) U29.A1(VOUT#A1) U29.B1(VOUT#B1)
N17135096: C118.1 R273.1(P1) R296.1(P1) U29.A2(VIN#A2) U29.B2(VIN#B2)
N17135910: R296.2(P2) U29.C2(ON)
N17144335: R152.1(P1) U46.3(R\E\S\E\T\)
N17156111: C129.2 R307.2(P2) U33.1(XIN/CLK) Y2.2
N17156113: C130.2 R307.1(P1) R308.2(P2) Y2.1
N17156222: R308.1(P1) U33.14(XOUT)
N17156522: R311.1 U33.11(Y1)
N17156525: R312.1 U33.9(Y2)
N17156528: R323.1 U33.8(Y3)
N17156983: R22.1(P1) U33.12(S2/SCL)
N17156986: R21.1(P1) U33.13(S1/SDA)
N17183635: R364.2(P2) U23.27(IN1)
N17183685: R70.2(P2) U23.25(IN2)
N17184172: R80.2(P2) R81.2(P2) U23.16(R\E\S\E\T\N\)
N17197007: J7.10(GND#10) R414.2(P2)
N17197255: C186.1 R414.1(P1) R426.1(P1) U8.2(A)
N17205778: C89.1 R505.1 U22.5(V+)
N17205782: C310.2 R207.2(P2) R510.1(P1) U22.1(VOUT)
N17205788: C310.1 R197.1(P1) R510.2(P2) U22.4(IN-)
N17205791: C91.1 R208.1(P1) R209.1(P1) R511.2(P2) U22.3(IN+)
N17205925: R104.2(P2) R109.2(P2) U11.AB13(ADC0_AIN4)
N17205949: R450.2(P2) R454.2(P2) U11.AA12(ADC0_AIN0)
N17209063: C92.1 R204.1 U19.5(V+)
N17209071: C298.2 R497.2(P2) R501.2(P2) R502.1(P1) U19.1(VOUT)
N17209083: C298.1 R203.1(P1) R502.2(P2) U19.4(IN-)
N17209089: C85.1 R191.2(P2) R195.1(P1) R196.1(P1) U19.3(IN+)
N17209568: C90.1 R201.1 U18.5(V+)
N17209576: C305.2 R188.2(P2) R189.2(P2) R506.1(P1) U18.1(VOUT)
N17209588: C305.1 R200.1(P1) R506.2(P2) U18.4(IN-)
N17209594: C86.1 R192.2(P2) R193.1(P1) R194.1(P1) U18.3(IN+)
N17210087: C101.1 R223.1 U24.5(V+)
N17210095: C331.2 R523.2(P2) R524.2(P2) R525.1(P1) U24.1(VOUT)
N17210107: C331.1 R222.1(P1) R525.2(P2) U24.4(IN-)
N17210113: C93.1 R210.1(P1) R211.1(P1) R212.2(P2) U24.3(IN+)
N17340888: TP21.1 U11.D20(VDD_MPU_MON)
N17722224: D2.2(ANODE) R20.1
N17757813: R133.1(P1) U45.4(1A1)
N17757815: R120.1(P1) U45.5(1A2)
N17758292: R119.1(P1) U49.7(B1)
N17758583: R376.2(P2) U41.7(B1)
N17758585: R381.2(P2) U41.6(B2)
N17814979: C293.1 R500.1 U56.1(IN)
N17839489: R187.2(P2) U23.24(EN2)
N17852592: R132.2(P2) U23.23(IN3)
N17852603: R138.2(P2) U23.22(EN3)
N17863265: J6.11 R310.1(P1)
N17863276: J6.12 R348.1(P1)
N17942790: TP20.1 U11.P21(VPP)
N17944182: C66.1 R149.1(P1) U11.AD5(VDDS_RTC)
N18003575: J16.20 R256.2(P2) R257.2(P2)
N18051330: R62.1(P1) U11.N20(SPI2_SCLK/EHRPWM4_TRIPZONE)
N18051447: R61.1(P1) U11.N25(SPI4_CS0/EHRPWM3_TRIPZONE)
N18051467: R60.1(P1) U11.P22(SPI2_D0/EHRPWM5_TRIPZONE)
N18074781: R64.2 U11.AA16(ADC1_AIN2)
N18074818: J2.1 U11.AE16(ADC1_AIN6)
N18074820: J2.2 U11.AD16(ADC1_AIN7)
N18075381: R478.2(P2) U11.AC18(CAM0_FIELD)
N18075410: R472.1(P1) R477.1(P1) SW1.1 SW1.2
N18075448: C262.1 R477.2(P2) R478.1(P1)
N18075562: R388.1(P1) U11.E25(GPIO5_12)
N18075603: R383.1(P1) U11.P20(SPI2_D1)
N18075606: R74.1(P1) U11.T23(SPI2_CS0)
N18139095: R300.1(P1) U32.7(WP)
N18167698: C99.2 U23.3(VCP)
N18181630: R73.1(P1) U11.P24(SPI4_D1/EHRPWM0_TRIPZONE_I)
N18182281: R363.2(P2) U23.26(EN1)
N18365828: Q1.D(DRAIN) Q2.G(GATE) R2.1(P1)
N18365970: Q2.D(DRAIN) R3.1(P1) U28.3(EN)
N18405849: R68.2 U11.AC16(ADC1_AIN0)
N18405956: R58.2 U11.AA15(ADC1_AIN4)
N21620210: C3.1 R295.2(P2) U4.3(IP0)
N21620213: C4.1 R294.2(P2) U4.5(IP1)
N21620216: C5.1 R293.2(P2) U4.7(IP2)
N21620219: C6.1 R292.2(P2) U4.9(IP3)
N21620222: C7.1 R291.2(P2) U4.11(IP4)
N21620225: C8.1 R290.2(P2) U4.18(IP5)
N21620228: C9.1 R289.2(P2) U4.20(IP6)
N21620231: C10.1 R288.2(P2) U4.22(IP7)
